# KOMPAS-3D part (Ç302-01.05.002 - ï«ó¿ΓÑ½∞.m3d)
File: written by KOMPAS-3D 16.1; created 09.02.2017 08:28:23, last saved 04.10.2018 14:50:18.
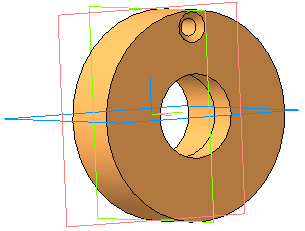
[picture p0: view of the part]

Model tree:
1. Эскиз:24
2. Операция вращения:2
     Угол 1 = 360
3. Фаска:1
     Угол = 45; Длина 1 = 0.5; Длина 2 = 0.5
4. Эскиз:25
5. Вырезать элемент выдавливания:1
     Расстояние 2 = 10; На расстояние 1 = 8
6. Фаска:2  (labels: Фторопласт-4  ГОСТ 10007-80 Е)
     Угол = 45; Длина 1 = 1.5; Длина 2 = 1.5

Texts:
  Линейный размер с обрывом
